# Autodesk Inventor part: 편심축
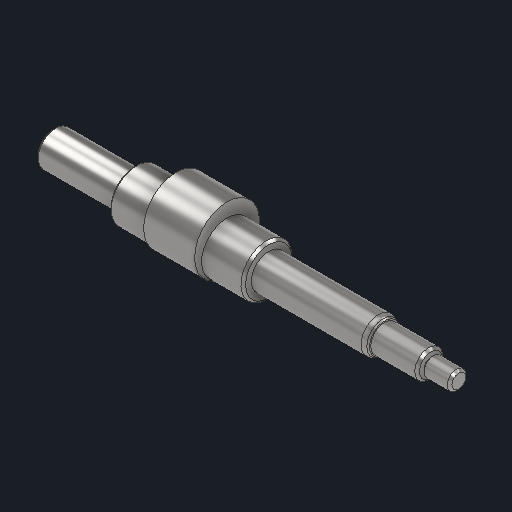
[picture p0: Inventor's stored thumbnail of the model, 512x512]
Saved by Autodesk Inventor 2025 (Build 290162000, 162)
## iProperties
Created: 2025-08
Part Number: 편심축
Material: 강철, 연강
Document SubType Name: Modeling
Designer: infra012
Density: 7.86 g/cm^3
Appearance: 기본값
Author: jhkim
Sending System: Autodesk Inventor 2026
Preprocessor: ST-DEVELOPER v20.1
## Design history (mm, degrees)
sketch "스케치1"
  geometry: 1 further point
  constraints: 1 other
feature "솔리드1"
node "솔리드2"
